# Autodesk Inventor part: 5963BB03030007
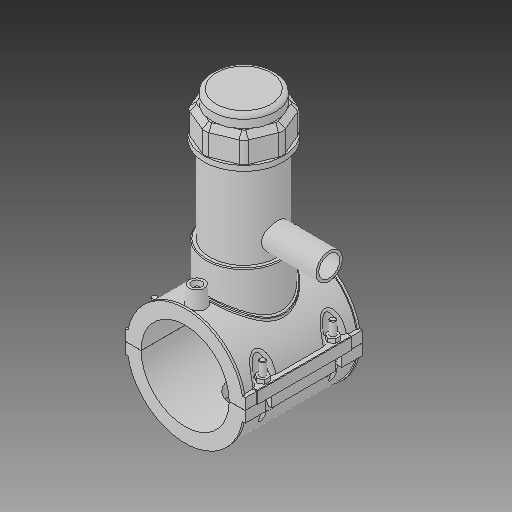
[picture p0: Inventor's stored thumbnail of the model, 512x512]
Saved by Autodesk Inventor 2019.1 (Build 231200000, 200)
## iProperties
Created: 2017-07
Part Number: 5963BB03030007
Material: Generic
Description: PLASSON TAPPING SADDLE 3''IPS x 1 3/4''IPS
Document SubType Name: Modeling
Designer: KIM
Mass: 1712.7 g
Surface Area: 2671.49 cm^2
Volume: 1712.7 cm^3
Density: 1 g/cm^3
Appearance: Default
Author: KIM
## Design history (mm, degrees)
derived "5963B.ipt"
feature "Solid1::5963B.ipt"
feature "Solid2::5963B.ipt"
feature "Solid4::5963B.ipt"
feature "Solid5::5963B.ipt"
tag "TaggingFeature1"
body "Solid1"
body "Solid2"
other parameters: "d0" = 88.7, "d2" = 120.904, "d3" = 22.175, "d4" = 118.11, "d5" = 0, "d6" = 0.1, "d8" = 0, "d19" = 6, "d20" = 6, "d21" = 70.866, "d23" = 0, "d24" = 35.433, "d26" = 0, "d29" = 3, "d30" = 29.56667, "d31" = 6, "d32" = 0, "d33" = 0, "d34" = 0.6, "d40" = 59.9612, "d41" = 79.83, "d43" = 0, "d45" = 0, "d47" = 128.521, "d70" = 15, "d72" = 0, "d73" = 6, "d75" = 5, "d76" = 0, "d77" = 4.435, "d78" = 74.35, "d79" = 15, "d80" = 47.244, "d82" = 5 deg, "d84" = 4, "d85" = 14, "d86" = 0, "d87" = 3, "d88" = 0, "d89" = 1, "d90" = 1, "d91" = 94.488, "d92" = 0, "d93" = 0.5, "d94" = 46.68421, "d96" = 117.6162, "d97" = 2.3622, "d98" = 0, "d102" = 0.887, "d120" = 140 deg, "d121" = 24.228, "d122" = 20 deg, "d123" = 230.62, "d124" = 69.186, "d126" = 0, "d143" = 91.361, "d145" = 20.46923, "d149" = 1.3305, "d150" = 22.51615, "d153" = 118.11, "d154" = 0, "d156" = 57.655, "d157" = 160 deg, "d159" = 5.322, "d161" = 1.3305, "d162" = 70.866, "d163" = 0, "d164" = 44.35, "d167" = 8.87, "d168" = 56.24878, "d170" = 3.2805, "d172" = 0, "d173" = 1, "d175" = 44.35, "d176" = 20 deg, "d177" = 6.209, "d178" = 26.61, "d180" = 0, "d183" = 10.644, "d184" = 4.9672, "d185" = 38.38575, "d186" = 38.38575, "d187" = 57.655, "d188" = 7.983, "d189" = 6.209, "d190" = 0, "d191" = 86.4825, "d193" = 6.1236, "d194" = 4.13385, "d195" = 90 deg, "d197" = 0, "d199" = 0, "d200" = 13.305, "d202" = 0, "d203" = 177.038, "d204" = 75.8385, "d205" = 55.881, "d206" = 67.8555, "d207" = 132.7785, "d208" = 138.08964, "d209" = 164.64534, "d210" = 68.6538, "d211" = 79.83, "d212" = 63.864, "d213" = 46.5516, "d216" = 0, "d217" = 8.87, "d218" = 4.435, "d219" = 0.887, "d222" = 88.7, "d224" = 0, "d230" = 5.322, "d233" = 6, "d236" = 60.452, "d237" = 35.433, "d238" = 6.02433, "d240" = 35.433, "d241" = 35.433, "d242" = 35.433, "d243" = 6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
